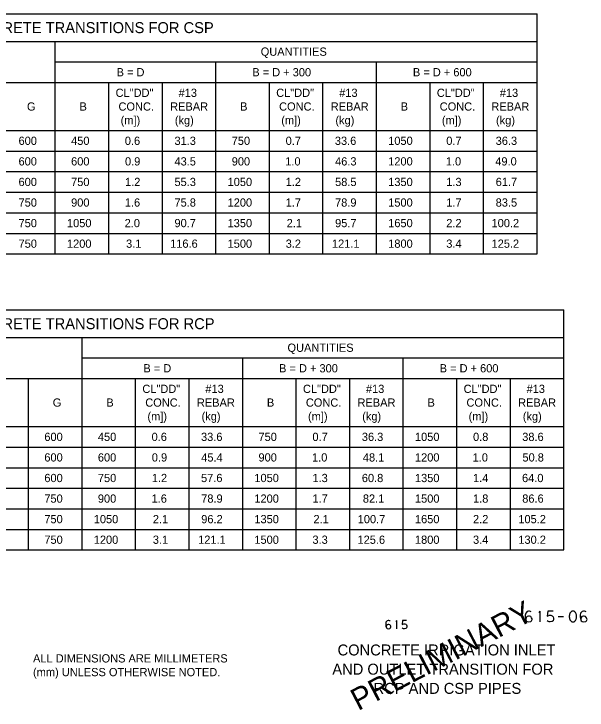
# Model space of a CAD drawing. Extents: x 49991.4 to 50043, y 49987.6 to 50011.4.
# Drawn here: x 50038.78 to 50042.95, y 49988.18 to 49993.25 of the extents above; entities that cross this region are included whole.
import ezdxf

# ---------------------------------------------------------------- set-up
doc = ezdxf.new("R2010")
doc.units = 0
doc.layers.add('Level 2', color=7, linetype='Continuous')

msp = doc.modelspace()

# ---------------------------------------------------------------- linework, layer by layer
at = {"layer": 'Level 2'}
for p, q in [((50035.1783, 49993.2523), (50042.5883, 49993.2523)), ((50035.1783, 49993.0523), (50042.5883, 49993.0523)), ((50039.0783, 49992.9023), (50042.5883, 49992.9023)), ((50035.1783, 49992.7523), (50042.5883, 49992.7523)), ((50035.1783, 49992.4023), (50042.5883, 49992.4023)), ((50035.1783, 49992.2523), (50042.5883, 49992.2523)), ((50035.1783, 49992.1023), (50042.5883, 49992.1023)), ((50035.1783, 49991.9523), (50042.5883, 49991.9523)), ((50035.1783, 49991.8023), (50042.5883, 49991.8023)), ((50035.1783, 49991.6523), (50042.5883, 49991.6523)), ((50035.1783, 49991.5023), (50042.5883, 49991.5023)), ((50042.6081, 49988.8987), (50042.6002, 49988.8848)), ((50042.6081, 49988.8987), (50042.6081, 49988.8187)), ((50041.5646, 49988.8293), (50041.5587, 49988.8189)), ((50041.5646, 49988.8293), (50041.5646, 49988.7693)), ((50042.7422, 49988.859), (50042.7813, 49988.859))]:
    msp.add_line(p, q, dxfattribs=at)
for points in [[(50042.5883, 49991.5023), (50042.5883, 49993.2523)], [(50039.0783, 49991.5023), (50039.0783, 49993.0523)], [(50040.2483, 49991.5023), (50040.2483, 49992.9023)], [(50041.4183, 49991.5023), (50041.4183, 49992.9023)], [(50039.4683, 49991.5023), (50039.4683, 49992.7523)], [(50039.8583, 49991.5023), (50039.8583, 49992.7523)], [(50040.6383, 49991.5023), (50040.6383, 49992.7523)], [(50041.0283, 49991.5023), (50041.0283, 49992.7523)], [(50041.8083, 49991.5023), (50041.8083, 49992.7523)], [(50042.1983, 49991.5023), (50042.1983, 49992.7523)], [(50034.9833, 49991.0937), (50042.7833, 49991.0937)], [(50042.7833, 49989.3437), (50042.7833, 49991.0937)], [(50034.9833, 49990.8937), (50042.7833, 49990.8937)], [(50039.2733, 49989.3437), (50039.2733, 49990.8937)], [(50039.2733, 49990.7437), (50042.7833, 49990.7437)], [(50040.4433, 49989.3437), (50040.4433, 49990.7437)], [(50041.6133, 49989.3437), (50041.6133, 49990.7437)], [(50034.9833, 49990.5937), (50042.7833, 49990.5937)], [(50038.8833, 49989.3437), (50038.8833, 49990.5937)], [(50039.6633, 49989.3437), (50039.6633, 49990.5937)], [(50040.0533, 49989.3437), (50040.0533, 49990.5937)], [(50040.8333, 49989.3437), (50040.8333, 49990.5937)], [(50041.2233, 49989.3437), (50041.2233, 49990.5937)], [(50042.0033, 49989.3437), (50042.0033, 49990.5937)], [(50042.3933, 49989.3437), (50042.3933, 49990.5937)], [(50034.9833, 49990.2437), (50042.7833, 49990.2437)], [(50034.9833, 49990.0937), (50042.7833, 49990.0937)], [(50034.9833, 49989.9437), (50042.7833, 49989.9437)], [(50034.9833, 49989.7937), (50042.7833, 49989.7937)], [(50034.9833, 49989.6437), (50042.7833, 49989.6437)], [(50034.9833, 49989.4937), (50042.7833, 49989.4937)], [(50034.9833, 49989.3437), (50042.7833, 49989.3437)], [(50042.5451, 49988.893), (50042.5407, 49988.8955), (50042.5331, 49988.8987), (50042.5255, 49988.8987), (50042.5155, 49988.8955), (50042.5048, 49988.8823), (50042.5022, 49988.8697), (50042.5022, 49988.8559), (50042.5035, 49988.8439), (50042.5085, 49988.8282), (50042.5155, 49988.8212), (50042.5255, 49988.8187), (50042.5419, 49988.8219), (50042.5482, 49988.8282), (50042.552, 49988.8376), (50042.5514, 49988.8426), (50042.5482, 49988.8502), (50042.5413, 49988.8584), (50042.5318, 49988.8609), (50042.5249, 49988.8615), (50042.5148, 49988.8584), (50042.5085, 49988.8508), (50042.5054, 49988.8382)], [(50042.7044, 49988.8987), (50042.6654, 49988.8987), (50042.6622, 49988.8609), (50042.6774, 49988.8678), (50042.6881, 49988.8678), (50042.6981, 49988.8641), (50042.7044, 49988.8571), (50042.7076, 49988.8477), (50042.7076, 49988.8376), (50042.7044, 49988.8275), (50042.6981, 49988.8212), (50042.6843, 49988.8187), (50042.6748, 49988.8187), (50042.6679, 49988.8212), (50042.6622, 49988.8282)], [(50042.849, 49988.8187), (50042.8518, 49988.8189), (50042.8545, 49988.8196), (50042.8572, 49988.8207), (50042.8598, 49988.8222), (50042.8622, 49988.8241), (50042.8646, 49988.8263), (50042.8667, 49988.829), (50042.8687, 49988.8319), (50042.8704, 49988.8352), (50042.8719, 49988.8387), (50042.8732, 49988.8424), (50042.8742, 49988.8463), (50042.8749, 49988.8504), (50042.8753, 49988.8545), (50042.8755, 49988.8587), (50042.8753, 49988.8629), (50042.8749, 49988.867), (50042.8742, 49988.8711), (50042.8732, 49988.875), (50042.8719, 49988.8787), (50042.8704, 49988.8822), (50042.8687, 49988.8855), (50042.8667, 49988.8884), (50042.8646, 49988.8911), (50042.8622, 49988.8933), (50042.8598, 49988.8952), (50042.8572, 49988.8967), (50042.8545, 49988.8978), (50042.8518, 49988.8985), (50042.849, 49988.8987), (50042.8462, 49988.8985), (50042.8435, 49988.8978), (50042.8408, 49988.8967), (50042.8382, 49988.8952), (50042.8358, 49988.8933), (50042.8334, 49988.8911), (50042.8313, 49988.8884), (50042.8293, 49988.8855), (50042.8276, 49988.8822), (50042.8261, 49988.8787), (50042.8248, 49988.875), (50042.8238, 49988.8711), (50042.8231, 49988.867), (50042.8227, 49988.8629), (50042.8225, 49988.8587), (50042.8227, 49988.8545), (50042.8231, 49988.8504), (50042.8238, 49988.8463), (50042.8248, 49988.8424), (50042.8261, 49988.8387), (50042.8276, 49988.8352), (50042.8293, 49988.8319), (50042.8313, 49988.829), (50042.8334, 49988.8263), (50042.8358, 49988.8241), (50042.8382, 49988.8222), (50042.8408, 49988.8207), (50042.8435, 49988.8196), (50042.8462, 49988.8189), (50042.849, 49988.8187)], [(50042.9451, 49988.893), (50042.9407, 49988.8955), (50042.9331, 49988.8987), (50042.9255, 49988.8987), (50042.9155, 49988.8955), (50042.9048, 49988.8823), (50042.9022, 49988.8697), (50042.9022, 49988.8559), (50042.9035, 49988.8439), (50042.9085, 49988.8282), (50042.9155, 49988.8212), (50042.9255, 49988.8187), (50042.9419, 49988.8219), (50042.9482, 49988.8282), (50042.952, 49988.8376), (50042.9514, 49988.8426), (50042.9482, 49988.8502), (50042.9413, 49988.8584), (50042.9318, 49988.8609), (50042.9249, 49988.8615), (50042.9148, 49988.8584), (50042.9085, 49988.8508), (50042.9054, 49988.8382)], [(50041.5174, 49988.825), (50041.5141, 49988.8269), (50041.5084, 49988.8293), (50041.5027, 49988.8293), (50041.4952, 49988.8269), (50041.4871, 49988.817), (50041.4852, 49988.8076), (50041.4852, 49988.7972), (50041.4862, 49988.7882), (50041.49, 49988.7764), (50041.4952, 49988.7712), (50041.5027, 49988.7693), (50041.515, 49988.7717), (50041.5197, 49988.7764), (50041.5226, 49988.7835), (50041.5221, 49988.7873), (50041.5197, 49988.7929), (50041.5145, 49988.7991), (50041.5074, 49988.801), (50041.5022, 49988.8014), (50041.4947, 49988.7991), (50041.49, 49988.7934), (50041.4876, 49988.7839)], [(50041.6369, 49988.8293), (50041.6076, 49988.8293), (50041.6052, 49988.801), (50041.6166, 49988.8061), (50041.6246, 49988.8061), (50041.6322, 49988.8033), (50041.6369, 49988.7981), (50041.6393, 49988.791), (50041.6393, 49988.7835), (50041.6369, 49988.7759), (50041.6322, 49988.7712), (50041.6218, 49988.7693), (50041.6147, 49988.7693), (50041.6095, 49988.7712), (50041.6052, 49988.7764)]]:
    msp.add_lwpolyline(points, dxfattribs=at)

# ---------------------------------------------------------------- texts
for s, height, p in [('METRIC INLET AND OUTLET CONCRETE TRANSITIONS FOR CSP', 0.08, (50036.898, 49993.1123)), ('QUANTITIES', 0.06, (50040.5747, 49992.9473)), ('B = D', 0.06, (50039.5247, 49992.7973)), ('B = D + 300', 0.06, (50040.5133, 49992.7973)), ('B = D + 600', 0.06, (50041.6833, 49992.7973)), ('CL"DD"', 0.06, (50039.5175, 49992.6473)), ('#13', 0.06, (50039.9763, 49992.6473)), ('CL"DD"', 0.06, (50040.6875, 49992.6473)), ('#13', 0.06, (50041.1463, 49992.6473)), ('CL"DD"', 0.06, (50041.8575, 49992.6473)), ('#13', 0.06, (50042.3163, 49992.6473)), ('G', 0.06, (50038.8718, 49992.5473)), ('B', 0.06, (50039.2547, 49992.5473)), ('CONC.', 0.06, (50039.5385, 49992.5473)), ('REBAR', 0.06, (50039.9147, 49992.5473)), ('B', 0.06, (50040.4247, 49992.5473)), ('CONC.', 0.06, (50040.7085, 49992.5473)), ('REBAR', 0.06, (50041.0847, 49992.5473)), ('B', 0.06, (50041.5947, 49992.5473)), ('CONC.', 0.06, (50041.8785, 49992.5473)), ('REBAR', 0.06, (50042.2547, 49992.5473)), ('(m])', 0.06, (50039.5543, 49992.4473)), ('(kg)', 0.06, (50039.9488, 49992.4473)), ('(m])', 0.06, (50040.7243, 49992.4473)), ('(kg)', 0.06, (50041.1188, 49992.4473)), ('(m])', 0.06, (50041.8943, 49992.4473)), ('(kg)', 0.06, (50042.2888, 49992.4473)), ('600', 0.06, (50038.8104, 49992.2973)), ('450', 0.06, (50039.1933, 49992.2973)), ('0.6', 0.06, (50039.5847, 49992.2973)), ('31.3', 0.06, (50039.9463, 49992.2973)), ('750', 0.06, (50040.3633, 49992.2973)), ('0.7', 0.06, (50040.7563, 49992.2973)), ('33.6', 0.06, (50041.1147, 49992.2973)), ('1050', 0.06, (50041.5033, 49992.2973)), ('0.7', 0.06, (50041.9263, 49992.2973)), ('36.3', 0.06, (50042.2863, 49992.2973)), ('600', 0.06, (50038.8104, 49992.1473)), ('600', 0.06, (50039.1933, 49992.1473)), ('0.9', 0.06, (50039.5861, 49992.1473)), ('43.5', 0.06, (50039.9463, 49992.1473)), ('900', 0.06, (50040.3633, 49992.1473)), ('1.0', 0.06, (50040.7533, 49992.1473)), ('46.3', 0.06, (50041.1163, 49992.1473)), ('1200', 0.06, (50041.5033, 49992.1473)), ('1.0', 0.06, (50041.9233, 49992.1473)), ('49.0', 0.06, (50042.2833, 49992.1473)), ('600', 0.06, (50038.8104, 49991.9973)), ('750', 0.06, (50039.1933, 49991.9973)), ('1.2', 0.06, (50039.5863, 49991.9973)), ('55.3', 0.06, (50039.9463, 49991.9973)), ('1050', 0.06, (50040.3333, 49991.9973)), ('1.2', 0.06, (50040.7563, 49991.9973)), ('58.5', 0.06, (50041.1163, 49991.9973)), ('1350', 0.06, (50041.5033, 49991.9973)), ('1.3', 0.06, (50041.9263, 49991.9973)), ('61.7', 0.06, (50042.2863, 49991.9973)), ('750', 0.06, (50038.8104, 49991.8473)), ('900', 0.06, (50039.1933, 49991.8473)), ('1.6', 0.06, (50039.5847, 49991.8473)), ('75.8', 0.06, (50039.9463, 49991.8473)), ('1200', 0.06, (50040.3333, 49991.8473)), ('1.7', 0.06, (50040.7563, 49991.8473)), ('78.9', 0.06, (50041.1161, 49991.8473)), ('1500', 0.06, (50041.5033, 49991.8473)), ('1.7', 0.06, (50041.9263, 49991.8473)), ('83.5', 0.06, (50042.2863, 49991.8473)), ('750', 0.06, (50038.8104, 49991.6973)), ('1050', 0.06, (50039.1633, 49991.6973)), ('2.0', 0.06, (50039.5833, 49991.6973)), ('90.7', 0.06, (50039.9463, 49991.6973)), ('1350', 0.06, (50040.3333, 49991.6973)), ('2.1', 0.06, (50040.7637, 49991.6973)), ('95.7', 0.06, (50041.1163, 49991.6973)), ('1650', 0.06, (50041.5033, 49991.6973)), ('2.2', 0.06, (50041.9263, 49991.6973)), ('100.2', 0.06, (50042.2563, 49991.6973)), ('750', 0.06, (50038.8104, 49991.5473)), ('1200', 0.06, (50039.1633, 49991.5473)), ('3.1', 0.06, (50039.5937, 49991.5473)), ('116.6', 0.06, (50039.9147, 49991.5473)), ('1500', 0.06, (50040.3333, 49991.5473)), ('3.2', 0.06, (50040.7563, 49991.5473)), ('121.1', 0.06, (50041.0937, 49991.5473)), ('1800', 0.06, (50041.5033, 49991.5473)), ('3.4', 0.06, (50041.9263, 49991.5473)), ('125.2', 0.06, (50042.2563, 49991.5473)), ('METRIC INLET AND OUTLET CONCRETE TRANSITIONS FOR RCP', 0.08, (50036.898, 49990.9537)), ('QUANTITIES', 0.06, (50040.7697, 49990.7887)), ('B = D', 0.06, (50039.7197, 49990.6387)), ('B = D + 300', 0.06, (50040.7083, 49990.6387)), ('B = D + 600', 0.06, (50041.8783, 49990.6387)), ('CL"DD"', 0.06, (50039.7125, 49990.4887)), ('#13', 0.06, (50040.1713, 49990.4887)), ('CL"DD"', 0.06, (50040.8825, 49990.4887)), ('#13', 0.06, (50041.3413, 49990.4887)), ('CL"DD"', 0.06, (50042.0525, 49990.4887)), ('#13', 0.06, (50042.5113, 49990.4887)), ('G', 0.06, (50039.0597, 49990.3887)), ('B', 0.06, (50039.4497, 49990.3887)), ('CONC.', 0.06, (50039.7335, 49990.3887)), ('REBAR', 0.06, (50040.1097, 49990.3887)), ('B', 0.06, (50040.6197, 49990.3887)), ('CONC.', 0.06, (50040.9035, 49990.3887)), ('REBAR', 0.06, (50041.2797, 49990.3887)), ('B', 0.06, (50041.7897, 49990.3887)), ('CONC.', 0.06, (50042.0735, 49990.3887)), ('REBAR', 0.06, (50042.4497, 49990.3887)), ('(m])', 0.06, (50039.7493, 49990.2887)), ('(kg)', 0.06, (50040.1438, 49990.2887)), ('(m])', 0.06, (50040.9193, 49990.2887)), ('(kg)', 0.06, (50041.3138, 49990.2887)), ('(m])', 0.06, (50042.0893, 49990.2887)), ('(kg)', 0.06, (50042.4838, 49990.2887)), ('600', 0.06, (50038.9983, 49990.1387)), ('450', 0.06, (50039.3883, 49990.1387)), ('0.6', 0.06, (50039.7797, 49990.1387)), ('33.6', 0.06, (50040.1397, 49990.1387)), ('750', 0.06, (50040.5583, 49990.1387)), ('0.7', 0.06, (50040.9513, 49990.1387)), ('36.3', 0.06, (50041.3113, 49990.1387)), ('1050', 0.06, (50041.6983, 49990.1387)), ('0.8', 0.06, (50042.1213, 49990.1387)), ('38.6', 0.06, (50042.4797, 49990.1387)), ('600', 0.06, (50038.9983, 49989.9887)), ('600', 0.06, (50039.3883, 49989.9887)), ('0.9', 0.06, (50039.7811, 49989.9887)), ('45.4', 0.06, (50040.1413, 49989.9887)), ('900', 0.06, (50040.5583, 49989.9887)), ('1.0', 0.06, (50040.9483, 49989.9887)), ('48.1', 0.06, (50041.3187, 49989.9887)), ('1200', 0.06, (50041.6983, 49989.9887)), ('1.0', 0.06, (50042.1183, 49989.9887)), ('50.8', 0.06, (50042.4813, 49989.9887)), ('600', 0.06, (50038.9983, 49989.8387)), ('750', 0.06, (50039.3883, 49989.8387)), ('1.2', 0.06, (50039.7813, 49989.8387)), ('57.6', 0.06, (50040.1397, 49989.8387)), ('1050', 0.06, (50040.5283, 49989.8387)), ('1.3', 0.06, (50040.9513, 49989.8387)), ('60.8', 0.06, (50041.3113, 49989.8387)), ('1350', 0.06, (50041.6983, 49989.8387)), ('1.4', 0.06, (50042.1213, 49989.8387)), ('64.0', 0.06, (50042.4783, 49989.8387)), ('750', 0.06, (50038.9983, 49989.6887)), ('900', 0.06, (50039.3883, 49989.6887)), ('1.6', 0.06, (50039.7797, 49989.6887)), ('78.9', 0.06, (50040.1411, 49989.6887)), ('1200', 0.06, (50040.5283, 49989.6887)), ('1.7', 0.06, (50040.9513, 49989.6887)), ('82.1', 0.06, (50041.3187, 49989.6887)), ('1500', 0.06, (50041.6983, 49989.6887)), ('1.8', 0.06, (50042.1213, 49989.6887)), ('86.6', 0.06, (50042.4797, 49989.6887)), ('750', 0.06, (50038.9983, 49989.5387)), ('1050', 0.06, (50039.3583, 49989.5387)), ('2.1', 0.06, (50039.7887, 49989.5387)), ('96.2', 0.06, (50040.1413, 49989.5387)), ('1350', 0.06, (50040.5283, 49989.5387)), ('2.1', 0.06, (50040.9587, 49989.5387)), ('100.7', 0.06, (50041.2813, 49989.5387)), ('1650', 0.06, (50041.6983, 49989.5387)), ('2.2', 0.06, (50042.1213, 49989.5387)), ('105.2', 0.06, (50042.4513, 49989.5387)), ('750', 0.06, (50038.9983, 49989.3887)), ('1200', 0.06, (50039.3583, 49989.3887)), ('3.1', 0.06, (50039.7887, 49989.3887)), ('121.1', 0.06, (50040.1187, 49989.3887)), ('1500', 0.06, (50040.5283, 49989.3887)), ('3.3', 0.06, (50040.9513, 49989.3887)), ('125.6', 0.06, (50041.2797, 49989.3887)), ('1800', 0.06, (50041.6983, 49989.3887)), ('3.4', 0.06, (50042.1213, 49989.3887)), ('130.2', 0.06, (50042.4513, 49989.3887)), ('CONCRETE IRRIGATION INLET', 0.08, (50041.1345, 49988.5747)), ('ALL DIMENSIONS ARE MILLIMETERS', 0.06, (50038.916, 49988.5236)), ('(mm) UNLESS OTHERWISE NOTED.', 0.06, (50038.916, 49988.4236)), ('AND OUTLET TRANSITION FOR', 0.08, (50041.0961, 49988.4347)), ('RCP AND CSP PIPES', 0.08, (50041.3966, 49988.2947))]:
    msp.add_text(s, height=height, dxfattribs=at).set_placement(p)
msp.add_text('PRELIMINARY', height=0.16, rotation=27.5, dxfattribs=at).set_placement((50041.2845, 49988.1684))

doc.saveas('drawing.dxf')
